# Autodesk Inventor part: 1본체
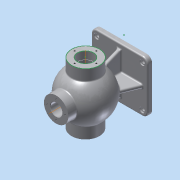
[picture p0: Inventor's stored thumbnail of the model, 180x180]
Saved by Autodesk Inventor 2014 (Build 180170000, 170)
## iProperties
Created: 2017-01
Part Number: 1본체
Material: Aluminum 6061
Document SubType Name: Modeling
Designer: ksu
Density: 2.71 g/cm^3
Appearance: Aluminum - Flat
Mass: 1509.03 g
Surface Area: 1155.13 cm^2
Volume: 556.837 cm^3
Author: ksu
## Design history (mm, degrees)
sketch "Sketch1"
  geometry: L1 (-62.5, 57.5)-(62.5, 57.5); L2 (62.5, 57.5)-(62.5, -57.5); L3 (62.5, -57.5)-(-62.5, -57.5); L4 (-62.5, -57.5)-(-62.5, 57.5); L5 (-62.5, 57.5)-(62.5, -57.5); L6 (62.5, 57.5)-(-62.5, -57.5); 1 further point
  constraints: 12 end point, 2 midpoint, 2 parallel, 1 horizontal, 1 perpendicular
  dimensions: "d0" = 125 distance of L2.end L3.end; "d1" = 115 distance of L1.end L2.end
extrude "Extrusion1" new body sketch "Sketch1" distance "d2" = 10; taper "d3" = 0 deg
sketch "Sketch2"
  geometry: L1 (0, 0)-(0, 85); L2 (-24.205, 37.85)-(24.205, 132.15); A1 r 53 centre (0, 85) between (-24.205, 37.85) and (24.205, 132.15)
  constraints: 4 end point, 2 point on circle, 1 centre point, 1 coincident, 1 midpoint, 1 vertical
  dimensions: "d4" = 85 distance of L1.start L1.end; "d5" = 106 diameter of A1
revolve "Revolution1" sketch "Sketch2" stored, may be unused: angle "d6" = 90 deg
workplane "Work Plane1"
sketch "Sketch3"
  geometry: C1 r 27 at (0, 0); 1 further point
  constraints: 1 centre point, 1 coincident
  dimensions: "d8" = 54 diameter of C1
extrude "Extrusion2" join sketch "Sketch3" distance "d9" = 65; taper "d10" = 0 deg
sketch "Sketch4"
  geometry: L1 (0, 0)-(0, 85); C1 r 31 at (0, 85)
  constraints: 2 end point, 1 centre point, 1 coincident, 1 vertical
  dimensions: "d11" = 85 distance of L1.start L1.end; "d12" = 62 diameter of C1
extrude "Extrusion3" join sketch "Sketch4" stored distance "d13" = 136; taper "d14" = 0 deg
sketch "Sketch5"
  geometry: L1 (-52.5, 10)-(-27.325, 72.31); L2 (-27.325, 72.31)-(0, 72.31); L3 (27.325, 72.31)-(0, 72.31); L4 (52.5, 10)-(27.325, 72.31); L5 (-52.5, 10)-(52.5, 10); 2 further points
  constraints: 10 end point
extrude "Extrusion4" join sketch "Sketch5" stored distance "d17" = 8; taper "d18" = 0 deg
sketch "Sketch6"
  geometry: L1 (57.5, 10)-(-57.5, 10) reference; L2 (-57.5, 10)-(-47.5, 10); L3 (-47.5, 10)-(-16.493, 86.744); L4 (-16.493, 86.744)-(0, 86.744); L5 (-47.5, 10)-(0, 10); L6 (47.5, 10)-(16.493, 86.744); L7 (16.493, 86.744)-(0, 86.744); L8 (47.5, 10)-(0, 10); 1 further point
  constraints: 14 end point, 1 midpoint, 1 parallel, 1 point on line
  dimensions: "d19" = 10 distance of L1.end L2.end; "d20" = 112 deg angle of L2 L3
extrude "Extrusion5" join sketch "Sketch6" stored distance "d21" = 8; taper "d22" = 0 deg
sketch "Sketch7"
  geometry: L1 (0, 0)-(0, 85); L2 (7.89, 42.73)-(-7.89, 127.27); A1 r 43 centre (0, 85) between (7.89, 42.73) and (-7.89, 127.27)
  constraints: 4 end point, 2 point on circle, 1 centre point, 1 coincident, 1 midpoint, 1 vertical
  dimensions: "d23" = 85 distance of L1.start L1.end; "d24" = 86 diameter of A1
revolve "Revolution2" sketch "Sketch7" stored, may be unused: angle "d25" = 90 deg
sketch "Sketch8"
  geometry: C1 r 31 at (0, 0) reference; C2 r 17.5 at (0, 0); 1 further point
  constraints: 1 centre point, 1 coincident
  dimensions: "d26" = 35 diameter of C2
extrude "Extrusion6" cut sketch "Sketch8" stored distance "d27" = 8; taper "d28" = 0 deg
sketch "Sketch9"
  geometry: C1 r 27 at (0, 0) reference; C2 r 13 at (0, 0)
  constraints: 1 centre point, 1 coincident
  dimensions: "d29" = 26 diameter of C2
extrude "Extrusion7" cut sketch "Sketch9" distance "d30" = 40; taper "d31" = 0 deg
sketch "Sketch10"
  geometry: 1 further point
sketch "Sketch11"
  geometry: L1 (68, 102.5)-(68, 67.5) reference; L2 (68, 85)-(52, 85); L3 (52, 85)-(52, 103.5); L4 (52, 103.5)-(50.25, 103.5); L5 (50.25, 103.5)-(50.25, 85); L6 (52, 85)-(50.25, 85); 1 further point
  constraints: 10 end point, 3 perpendicular, 1 midpoint, 1 parallel
  dimensions: "d32" = 16 distance of L2.start L2.end; "d33" = 18.5 distance of L2.end L3.end; "d34" = 1.75 distance of L3.end L4.end
revolve "Revolution3" sketch "Sketch11" stored, may be unused: angle "d36" = 90 deg
sketch "Sketch13"
  geometry: 1 further point
workplane "Work Plane2"
sketch "Sketch15"
  geometry: 1 further point
sketch "Sketch16"
  geometry: C1 r 17.5 at (0, 0) reference; C2 r 31 at (0, 0) reference; 1 further point
sketch "Sketch17"
  geometry: L1 (0, 0)-(0, 24); C1 r 31 at (0, 0) reference; 2 further points
  constraints: 2 end point, 1 coincident, 1 vertical
  dimensions: "d42" = 24 distance of L1.start L1.end
hole "Hole1" sketch "Sketch17" at (0, 24) diameter "d43" = 3.459; stored, may be unused: countersink angle "d47" = 90 deg, drill point angle "d49" = 118 deg; dims "d44" = 16, "d45" = 4, "d46" = 2, "d48" = 19
workaxis "Work Axis1"
pattern_circular "Circular Pattern1" dims angle "d51" = 360 deg
sketch "Sketch18"
  geometry: L1 (0, 0)-(0, 22.5); C1 r 31 at (0, 0) reference; 2 further points
  constraints: 2 end point, 1 coincident, 1 vertical
  dimensions: "d53" = 22.5 distance of L1.start L1.end
hole "Hole2" sketch "Sketch18" at (0, 22.5) diameter "d54" = 3.459; stored, may be unused: countersink angle "d58" = 90 deg, drill point angle "d60" = 118 deg; dims "d55" = 12, "d56" = 4, "d57" = 2, "d59" = 15
pattern_circular "Circular Pattern2" dims angle "d62" = 360 deg
sketch "Sketch19"
  geometry: L1 (0, 0)-(0, 20); C1 r 27 at (0, 0) reference; 1 further point
  constraints: 2 end point, 1 coincident, 1 vertical
  dimensions: "d64" = 20 distance of L1.start L1.end
hole "Hole3" sketch "Sketch19" at (0, 20) diameter "d65" = 3.459; stored, may be unused: countersink angle "d69" = 90 deg, drill point angle "d71" = 118 deg; dims "d66" = 9, "d67" = 4, "d68" = 2, "d70" = 11
workaxis "Work Axis2"
pattern_circular "Circular Pattern3" dims angle "d73" = 360 deg
sketch "Sketch20"
  geometry: L1 (-50.5, -45.5)-(50.5, -45.5); L2 (50.5, -45.5)-(50.5, 45.5); L3 (50.5, 45.5)-(-50.5, 45.5); L4 (-50.5, 45.5)-(-50.5, -45.5); L5 (-50.5, -45.5)-(50.5, 45.5); L6 (50.5, -45.5)-(-50.5, 45.5); 5 further points
  constraints: 12 end point, 4 coincident, 2 midpoint, 2 parallel, 1 horizontal, 1 perpendicular
  dimensions: "d75" = 101 distance of L3.end L2.end; "d76" = 91 distance of L2.end L1.end
hole "Hole4" sketch "Sketch20" at (-50.5, 45.5), (-50.5, -45.5), (50.5, -45.5), (50.5, 45.5) diameter "d77" = 8; stored, may be unused: countersink angle "d81" = 90 deg, drill point angle "d83" = 118 deg; dims "d78" = 9, "d79" = 12, "d80" = 3, "d82" = 10
fillet "Fillet1" dims "d84" = 12
fillet "Fillet2" dims "d85" = 3
fillet "Fillet3" dims "d86" = 3
chamfer "Chamfer1" distance "d87" = 1; stored, may be unused: second distance "d88" = 2, angle "d89" = 45 deg
workplane "Work Plane3"
sketch "Sketch21"
  geometry: L1 (27, 150)-(-27, 150) reference; L2 (-20.739, 143.002)-(20.739, 143.002); L3 (20.739, 143.002)-(20.739, 136.998); L4 (20.739, 136.998)-(-20.739, 136.998); L5 (-20.739, 136.998)-(-20.739, 143.002); L6 (0, 150)-(0, 140); L7 (-20.739, 140)-(20.739, 140); L8 (0, 143.002)-(0, 136.998); 2 further points
  constraints: 6 end point, 6 midpoint, 1 parallel, 2 other
  dimensions: "d91" = 10 distance of L6.start L6.end
emboss "Emboss2" sketch "Sketch21" dims "d92" = 0.5, "d93" = 0
fillet "Fillet4" dims "d94" = 3
body "Solid1"
other parameters: "d7" = 85
